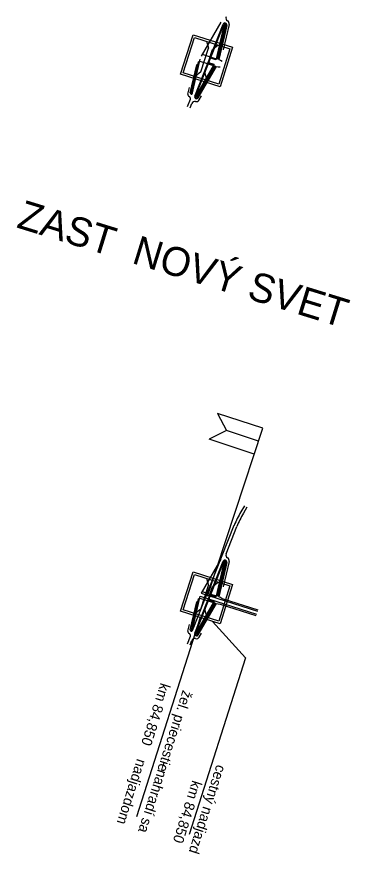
# Model space of a CAD drawing. Extents: x -566241 to -446826, y -1330151 to -1274078.
# Drawn here: x -545740 to -544934, y -1276105 to -1274078 of the extents above; entities that cross this region are included whole.
import ezdxf

# ---------------------------------------------------------------- set-up
doc = ezdxf.new("R2010")
doc.units = 0
for name, color, linetype in [('1-POPIS', 7, 'Continuous'), ('priecestia', 7, 'Continuous'), ('STANICE', 7, 'Continuous')]:
    doc.layers.add(name, color=color, linetype=linetype)

msp = doc.modelspace()

# ---------------------------------------------------------------- linework, layer by layer
at = {"layer": '1-POPIS'}
for p, q in [((-545294.7, -1274211.5), (-545276.5, -1274154.3)), ((-545281.4, -1274137), (-545276.5, -1274154.3)), ((-545266.9, -1274157.3), (-545252.8, -1274146.1)), ((-545285.2, -1274214.5), (-545266.9, -1274157.3)), ((-545304.6, -1274194.3), (-545301.4, -1274192.2)), ((-545300.1, -1274186.8), (-545297.3, -1274185.3)), ((-545294.7, -1274211.5), (-545308.8, -1274222.7)), ((-545285.2, -1274214.5), (-545280.2, -1274231.8)), ((-545281.4, -1275437), (-545276.5, -1275454.3)), ((-545266.9, -1275457.3), (-545252.8, -1275446.1)), ((-545294.7, -1275511.5), (-545276.5, -1275454.3)), ((-545285.2, -1275514.5), (-545266.9, -1275457.3)), ((-545304.6, -1275494.3), (-545301.4, -1275492.2)), ((-545300.1, -1275486.8), (-545297.3, -1275485.3)), ((-545294.7, -1275511.5), (-545308.8, -1275522.7)), ((-545285.2, -1275514.5), (-545280.2, -1275531.8)), ((-545296, -1275532), (-545449.9, -1276014.7)), ((-545186.5, -1275630), (-545266.6, -1275541.4)), ((-545186.5, -1275630), (-545322.8, -1276057.3))]:
    msp.add_line(p, q, dxfattribs=at)
for points in [[(-545238.4, -1274095.8), (-545236.7, -1274099.4), (-545233.7, -1274097.7)], [(-545264.1, -1274195.9), (-545264.2, -1274201), (-545259.2, -1274197.4)], [(-545252.9, -1274181), (-545254.6, -1274177.1), (-545257.7, -1274179.5)], [(-545315.9, -1274265.1), (-545317.6, -1274262.4), (-545320.2, -1274263.4)], [(-545307.9, -1274271.7), (-545304, -1274270), (-545303.3, -1274273.5)], [(-545238.4, -1275395.8), (-545236.7, -1275399.4), (-545233.7, -1275397.7)], [(-545252.9, -1275481), (-545254.6, -1275477.1), (-545257.7, -1275479.5)], [(-545264.1, -1275495.9), (-545264.2, -1275501), (-545259.2, -1275497.4)], [(-545315.9, -1275565.1), (-545317.6, -1275562.4), (-545320.2, -1275563.4)], [(-545307.9, -1275571.7), (-545304, -1275570), (-545303.3, -1275573.5)]]:
    msp.add_lwpolyline(points, dxfattribs=at)
for points in [[(-545313.3, -1274121.6), (-545218, -1274151.9), (-545248.4, -1274247.2), (-545343.6, -1274216.8)], [(-545310, -1274127.9), (-545224.3, -1274155.2), (-545251.6, -1274240.9), (-545337.4, -1274213.6)], [(-545313.3, -1275421.6), (-545218, -1275451.9), (-545248.4, -1275547.2), (-545343.6, -1275516.8)], [(-545310, -1275427.9), (-545224.3, -1275455.2), (-545251.6, -1275540.9), (-545337.4, -1275513.6)]]:
    msp.add_lwpolyline(points, close=True, dxfattribs=at)
for centre, radius, start, end in [((-545236.5, -1274097.7), 4.7, 347.0136, 158.4519), ((-545236.5, -1274097.7), 2.7, 347.0136, 158.4519), ((-545226.3, -1274080.9), 8, 158.4519, 240.8481), ((-545234.1, -1274094.8), 8, 347.0136, 60.8481), ((-545321.3, -1274266.2), 5, 166.9081, 250.1701), ((-545324.7, -1274275.6), 5, 338.4519, 70.1701), ((-545317.4, -1274262.5), 3, 166.9081, 338.4519), ((-545305.2, -1274271.6), 4.7, 158.4519, 329.9957), ((-545305.2, -1274271.6), 2.7, 158.4519, 329.9957), ((-545309.2, -1274290.9), 8, 76.0327, 158.4519), ((-545305.4, -1274275.4), 8, 256.0327, 329.9957), ((-545236.5, -1275397.7), 4.7, 347.0136, 158.4519), ((-545226.3, -1275380.9), 8, 158.4519, 240.8481), ((-545234.1, -1275394.8), 8, 347.0136, 60.8481), ((-545236.5, -1275397.7), 2.7, 347.0136, 158.4519), ((-545321.3, -1275566.2), 5, 166.9081, 250.1701), ((-545324.7, -1275575.6), 5, 338.4519, 70.1701), ((-545317.4, -1275562.5), 3, 166.9081, 338.4519), ((-545305.2, -1275571.6), 4.7, 158.4519, 329.9957), ((-545305.2, -1275571.6), 2.7, 158.4519, 329.9957), ((-545309.2, -1275590.9), 8, 76.0327, 158.4519), ((-545305.4, -1275575.4), 8, 256.0327, 329.9957)]:
    msp.add_arc(centre, radius, start, end, dxfattribs=at)
at = {"layer": 'priecestia'}
for p, q in [((-545246.5, -1274091.1), (-545294, -1274173.1)), ((-545238.4, -1274095.8), (-545257.7, -1274179.5)), ((-545309.5, -1274269.9), (-545240.9, -1274096)), ((-545307.7, -1274270.6), (-545239, -1274096.7)), ((-545236.7, -1274099.4), (-545254.6, -1274177.1)), ((-545233.9, -1274098.3), (-545252.9, -1274181)), ((-545231.9, -1274098.8), (-545251, -1274181.6)), ((-545226.3, -1274096.6), (-545240.4, -1274157.7)), ((-545291.5, -1274168.7), (-545257.7, -1274179.5)), ((-545270.4, -1274177), (-545270.9, -1274178.4)), ((-545270.4, -1274177), (-545270.7, -1274176.9)), ((-545258, -1274180.9), (-545270.4, -1274177)), ((-545320.3, -1274261.8), (-545304.6, -1274194.3)), ((-545317.6, -1274262.4), (-545300.1, -1274186.8)), ((-545315.9, -1274265.1), (-545296.2, -1274180.4)), ((-545307.9, -1274271.7), (-545264.1, -1274195.9)), ((-545297.3, -1274185.3), (-545259.2, -1274197.4)), ((-545275.7, -1274190.6), (-545276, -1274190.5)), ((-545275.2, -1274189.2), (-545275.7, -1274190.6)), ((-545263.3, -1274194.5), (-545275.7, -1274190.6)), ((-545275.2, -1274189.2), (-545275.5, -1274189.1)), ((-545275, -1274189.2), (-545275.5, -1274190.7)), ((-545262.9, -1274193.1), (-545275.2, -1274189.2)), ((-545274.8, -1274189.3), (-545275.2, -1274190.7)), ((-545274.5, -1274189.4), (-545275, -1274190.8)), ((-545274.3, -1274189.5), (-545274.7, -1274190.9)), ((-545274, -1274189.5), (-545274.5, -1274191)), ((-545273.8, -1274189.6), (-545274.3, -1274191)), ((-545273.6, -1274189.7), (-545274, -1274191.1)), ((-545273.3, -1274189.8), (-545273.8, -1274191.2)), ((-545273.1, -1274189.8), (-545273.5, -1274191.3)), ((-545272.9, -1274189.9), (-545273.3, -1274191.4)), ((-545271.9, -1274190.2), (-545272.4, -1274191.7)), ((-545271.7, -1274190.3), (-545272.1, -1274191.7)), ((-545271.4, -1274190.4), (-545271.9, -1274191.8)), ((-545271.2, -1274190.5), (-545271.6, -1274191.9)), ((-545271, -1274190.5), (-545271.4, -1274192)), ((-545270.9, -1274178.4), (-545271.2, -1274178.3)), ((-545270.7, -1274190.6), (-545271.2, -1274192)), ((-545258.5, -1274182.4), (-545270.9, -1274178.4)), ((-545270.5, -1274190.7), (-545270.9, -1274192.1)), ((-545270.2, -1274190.8), (-545270.7, -1274192.2)), ((-545270.2, -1274177.1), (-545270.6, -1274178.5)), ((-545270, -1274190.8), (-545270.5, -1274192.3)), ((-545270, -1274177.1), (-545270.4, -1274178.6)), ((-545269.7, -1274177.2), (-545270.2, -1274178.6)), ((-545269.8, -1274190.9), (-545270.2, -1274192.3)), ((-545269.5, -1274191), (-545270, -1274192.4)), ((-545269.5, -1274177.3), (-545269.9, -1274178.7)), ((-545269.2, -1274177.4), (-545269.7, -1274178.8)), ((-545269, -1274177.4), (-545269.5, -1274178.9)), ((-545268.8, -1274177.5), (-545269.2, -1274179)), ((-545268.5, -1274177.6), (-545269, -1274179)), ((-545268.6, -1274191.3), (-545269, -1274192.7)), ((-545268.3, -1274191.4), (-545268.8, -1274192.8)), ((-545268.3, -1274177.7), (-545268.7, -1274179.1)), ((-545268, -1274177.7), (-545268.5, -1274179.2)), ((-545268.1, -1274191.4), (-545268.5, -1274192.9)), ((-545267.9, -1274191.5), (-545268.3, -1274192.9)), ((-545267.6, -1274191.6), (-545268.1, -1274193)), ((-545267.4, -1274191.7), (-545267.8, -1274193.1)), ((-545267.1, -1274178.1), (-545267.6, -1274179.5)), ((-545267.1, -1274191.7), (-545267.6, -1274193.2)), ((-545266.9, -1274191.8), (-545267.4, -1274193.3)), ((-545266.9, -1274178.1), (-545267.3, -1274179.6)), ((-545266.6, -1274178.2), (-545267.1, -1274179.6)), ((-545266.7, -1274191.9), (-545267.1, -1274193.3)), ((-545266.4, -1274192), (-545266.9, -1274193.4)), ((-545266.4, -1274178.3), (-545266.8, -1274179.7)), ((-545266.1, -1274178.4), (-545266.6, -1274179.8)), ((-545266.2, -1274192.1), (-545266.6, -1274193.5)), ((-545265.9, -1274178.4), (-545266.4, -1274179.9)), ((-545265.7, -1274178.5), (-545266.1, -1274179.9)), ((-545265.4, -1274178.6), (-545265.9, -1274180)), ((-545265.2, -1274192.4), (-545265.7, -1274193.8)), ((-545265.2, -1274178.7), (-545265.6, -1274180.1)), ((-545265, -1274192.4), (-545265.5, -1274193.9)), ((-545265, -1274178.7), (-545265.4, -1274180.2)), ((-545264.7, -1274178.8), (-545265.2, -1274180.2)), ((-545264.8, -1274192.5), (-545265.2, -1274193.9)), ((-545264.5, -1274192.6), (-545265, -1274194)), ((-545264.3, -1274192.7), (-545264.7, -1274194.1)), ((-545264, -1274192.7), (-545264.5, -1274194.2)), ((-545263.8, -1274192.8), (-545264.3, -1274194.2)), ((-545263.8, -1274179.1), (-545264.2, -1274180.5)), ((-545263.5, -1274179.2), (-545264, -1274180.6)), ((-545263.6, -1274192.9), (-545264, -1274194.3)), ((-545263.3, -1274193), (-545263.8, -1274194.4)), ((-545263.3, -1274179.3), (-545263.7, -1274180.7)), ((-545263, -1274179.3), (-545263.5, -1274180.8)), ((-545263.1, -1274193), (-545263.5, -1274194.5)), ((-545262.8, -1274179.4), (-545263.3, -1274180.8)), ((-545262.9, -1274193.1), (-545263.3, -1274194.5)), ((-545262.6, -1274179.5), (-545263, -1274180.9)), ((-545262.3, -1274179.6), (-545262.8, -1274181)), ((-545262.1, -1274179.6), (-545262.5, -1274181.1)), ((-545261.9, -1274179.7), (-545262.3, -1274181.2)), ((-545261.6, -1274179.8), (-545262.1, -1274181.2)), ((-545261.4, -1274179.9), (-545261.8, -1274181.3)), ((-545260.4, -1274180.2), (-545260.9, -1274181.6)), ((-545260.2, -1274180.3), (-545260.6, -1274181.7)), ((-545259.9, -1274180.3), (-545260.4, -1274181.8)), ((-545259.7, -1274180.4), (-545260.2, -1274181.8)), ((-545259.5, -1274180.5), (-545259.9, -1274181.9)), ((-545259.2, -1274180.6), (-545259.7, -1274182)), ((-545259, -1274180.6), (-545259.5, -1274182.1)), ((-545258.8, -1274180.7), (-545259.2, -1274182.1)), ((-545258.5, -1274180.8), (-545259, -1274182.2)), ((-545258.3, -1274180.9), (-545258.7, -1274182.3)), ((-545258, -1274180.9), (-545258.5, -1274182.4)), ((-545251, -1274181.6), (-545247.1, -1274182.9)), ((-545247.1, -1274182.9), (-545242.8, -1274185.8)), ((-545304, -1274270), (-545264.2, -1274201)), ((-545302.8, -1274273), (-545259.2, -1274197.4)), ((-545301.1, -1274274), (-545257.2, -1274198)), ((-545257.2, -1274198), (-545253.2, -1274199.3)), ((-545253.2, -1274199.3), (-545248, -1274199.4)), ((-545326.2, -1274265.1), (-545322.4, -1274248.9)), ((-545327.2, -1274295.4), (-545320, -1274277.4)), ((-545307.7, -1274275.4), (-545307.7, -1274275.4)), ((-545298.4, -1274279.4), (-545292.8, -1274269.6)), ((-545320.6, -1274298), (-545316.7, -1274288)), ((-545189.4, -1275261.7), (-545197.9, -1275276.1)), ((-545183.4, -1275265.3), (-545191.6, -1275279.2)), ((-545314.6, -1275563.6), (-545214, -1275308.9)), ((-545233.7, -1275377.9), (-545207.7, -1275312)), ((-545246.5, -1275391.1), (-545294, -1275473.1)), ((-545309.5, -1275569.9), (-545240.9, -1275396)), ((-545307.7, -1275570.6), (-545239, -1275396.7)), ((-545238.4, -1275395.8), (-545257.7, -1275479.5)), ((-545236.7, -1275399.4), (-545254.6, -1275477.1)), ((-545233.9, -1275398.3), (-545252.9, -1275481)), ((-545231.9, -1275398.8), (-545251, -1275481.6)), ((-545226.3, -1275396.6), (-545240.4, -1275457.7)), ((-545294, -1275473.1), (-545158, -1275516.5)), ((-545291.5, -1275468.7), (-545257.7, -1275479.5)), ((-545320.3, -1275561.8), (-545304.6, -1275494.3)), ((-545317.6, -1275562.4), (-545300.1, -1275486.8)), ((-545315.9, -1275565.1), (-545296.2, -1275480.4)), ((-545297.3, -1275485.3), (-545259.2, -1275497.4)), ((-545296.2, -1275480.4), (-545160.3, -1275523.7)), ((-545275.7, -1275490.6), (-545276, -1275490.5)), ((-545275.2, -1275489.2), (-545275.7, -1275490.6)), ((-545263.3, -1275494.5), (-545275.7, -1275490.6)), ((-545275.2, -1275489.2), (-545275.5, -1275489.1)), ((-545275, -1275489.2), (-545275.5, -1275490.7)), ((-545262.9, -1275493.1), (-545275.2, -1275489.2)), ((-545274.8, -1275489.3), (-545275.2, -1275490.7)), ((-545274.5, -1275489.4), (-545275, -1275490.8)), ((-545274.3, -1275489.5), (-545274.7, -1275490.9)), ((-545274, -1275489.5), (-545274.5, -1275491)), ((-545273.8, -1275489.6), (-545274.3, -1275491)), ((-545273.6, -1275489.7), (-545274, -1275491.1)), ((-545273.3, -1275489.8), (-545273.8, -1275491.2)), ((-545273.1, -1275489.8), (-545273.5, -1275491.3)), ((-545272.9, -1275489.9), (-545273.3, -1275491.4)), ((-545271.9, -1275490.2), (-545272.4, -1275491.7)), ((-545271.7, -1275490.3), (-545272.1, -1275491.7)), ((-545271.4, -1275490.4), (-545271.9, -1275491.8)), ((-545271.2, -1275490.5), (-545271.6, -1275491.9)), ((-545271, -1275490.5), (-545271.4, -1275492)), ((-545270.9, -1275478.4), (-545271.2, -1275478.3)), ((-545270.7, -1275490.6), (-545271.2, -1275492)), ((-545270.4, -1275477), (-545270.9, -1275478.4)), ((-545258.5, -1275482.4), (-545270.9, -1275478.4)), ((-545270.5, -1275490.7), (-545270.9, -1275492.1)), ((-545270.4, -1275477), (-545270.7, -1275476.9)), ((-545270.2, -1275490.8), (-545270.7, -1275492.2)), ((-545270.2, -1275477.1), (-545270.6, -1275478.5)), ((-545270, -1275490.8), (-545270.5, -1275492.3)), ((-545258, -1275480.9), (-545270.4, -1275477)), ((-545270, -1275477.1), (-545270.4, -1275478.6)), ((-545269.7, -1275477.2), (-545270.2, -1275478.6)), ((-545269.8, -1275490.9), (-545270.2, -1275492.3)), ((-545269.5, -1275491), (-545270, -1275492.4)), ((-545269.5, -1275477.3), (-545269.9, -1275478.7)), ((-545269.2, -1275477.4), (-545269.7, -1275478.8)), ((-545269, -1275477.4), (-545269.5, -1275478.9)), ((-545268.8, -1275477.5), (-545269.2, -1275479)), ((-545268.5, -1275477.6), (-545269, -1275479)), ((-545268.6, -1275491.3), (-545269, -1275492.7)), ((-545268.3, -1275491.4), (-545268.8, -1275492.8)), ((-545268.3, -1275477.7), (-545268.7, -1275479.1)), ((-545268, -1275477.7), (-545268.5, -1275479.2)), ((-545268.1, -1275491.4), (-545268.5, -1275492.9)), ((-545267.9, -1275491.5), (-545268.3, -1275492.9)), ((-545267.6, -1275491.6), (-545268.1, -1275493)), ((-545267.4, -1275491.7), (-545267.8, -1275493.1)), ((-545267.1, -1275478.1), (-545267.6, -1275479.5)), ((-545267.1, -1275491.7), (-545267.6, -1275493.2)), ((-545266.9, -1275491.8), (-545267.4, -1275493.3)), ((-545266.9, -1275478.1), (-545267.3, -1275479.6)), ((-545266.6, -1275478.2), (-545267.1, -1275479.6)), ((-545266.7, -1275491.9), (-545267.1, -1275493.3)), ((-545266.4, -1275492), (-545266.9, -1275493.4)), ((-545266.4, -1275478.3), (-545266.8, -1275479.7)), ((-545266.1, -1275478.4), (-545266.6, -1275479.8)), ((-545266.2, -1275492.1), (-545266.6, -1275493.5)), ((-545265.9, -1275478.4), (-545266.4, -1275479.9)), ((-545265.7, -1275478.5), (-545266.1, -1275479.9)), ((-545265.4, -1275478.6), (-545265.9, -1275480)), ((-545265.2, -1275492.4), (-545265.7, -1275493.8)), ((-545265.2, -1275478.7), (-545265.6, -1275480.1)), ((-545265, -1275492.4), (-545265.5, -1275493.9)), ((-545265, -1275478.7), (-545265.4, -1275480.2)), ((-545264.7, -1275478.8), (-545265.2, -1275480.2)), ((-545264.8, -1275492.5), (-545265.2, -1275493.9)), ((-545264.5, -1275492.6), (-545265, -1275494)), ((-545264.3, -1275492.7), (-545264.7, -1275494.1)), ((-545264, -1275492.7), (-545264.5, -1275494.2)), ((-545263.8, -1275492.8), (-545264.3, -1275494.2)), ((-545263.8, -1275479.1), (-545264.2, -1275480.5)), ((-545263.5, -1275479.2), (-545264, -1275480.6)), ((-545263.6, -1275492.9), (-545264, -1275494.3)), ((-545263.3, -1275493), (-545263.8, -1275494.4)), ((-545263.3, -1275479.3), (-545263.7, -1275480.7)), ((-545263, -1275479.3), (-545263.5, -1275480.8)), ((-545263.1, -1275493), (-545263.5, -1275494.5)), ((-545262.8, -1275479.4), (-545263.3, -1275480.8)), ((-545262.9, -1275493.1), (-545263.3, -1275494.5)), ((-545262.6, -1275479.5), (-545263, -1275480.9)), ((-545262.3, -1275479.6), (-545262.8, -1275481)), ((-545262.1, -1275479.6), (-545262.5, -1275481.1)), ((-545261.9, -1275479.7), (-545262.3, -1275481.2)), ((-545261.6, -1275479.8), (-545262.1, -1275481.2)), ((-545261.4, -1275479.9), (-545261.8, -1275481.3)), ((-545260.4, -1275480.2), (-545260.9, -1275481.6)), ((-545260.2, -1275480.3), (-545260.6, -1275481.7)), ((-545259.9, -1275480.3), (-545260.4, -1275481.8)), ((-545259.7, -1275480.4), (-545260.2, -1275481.8)), ((-545259.5, -1275480.5), (-545259.9, -1275481.9)), ((-545259.2, -1275480.6), (-545259.7, -1275482)), ((-545259, -1275480.6), (-545259.5, -1275482.1)), ((-545258.8, -1275480.7), (-545259.2, -1275482.1)), ((-545258.5, -1275480.8), (-545259, -1275482.2)), ((-545258.3, -1275480.9), (-545258.7, -1275482.3)), ((-545258, -1275480.9), (-545258.5, -1275482.4)), ((-545251, -1275481.6), (-545247.1, -1275482.9)), ((-545247.1, -1275482.9), (-545242.8, -1275485.8)), ((-545242.8, -1275485.8), (-545156.9, -1275513.2)), ((-545307.9, -1275571.7), (-545264.1, -1275495.9)), ((-545304, -1275570), (-545264.2, -1275501)), ((-545302.8, -1275573), (-545259.2, -1275497.4)), ((-545301.1, -1275574), (-545257.2, -1275498)), ((-545257.2, -1275498), (-545253.2, -1275499.3)), ((-545253.2, -1275499.3), (-545248, -1275499.4)), ((-545248, -1275499.4), (-545161.4, -1275527)), ((-545326.2, -1275565.1), (-545322.4, -1275548.9)), ((-545307.7, -1275575.4), (-545307.7, -1275575.4)), ((-545298.4, -1275579.4), (-545292.8, -1275569.6)), ((-545327.2, -1275595.4), (-545320, -1275577.4)), ((-545320.6, -1275598), (-545316.7, -1275588))]:
    msp.add_line(p, q, dxfattribs=at)
for centre in [(-545000.1, -1275393.4), (-544993.8, -1275396.5)]:
    msp.add_arc(centre, 230, 149.3459, 158.4519, dxfattribs=at)
at = {"layer": 'STANICE'}
for p, q in [((-545145.1, -1275073.6), (-545254.1, -1275037.9)), ((-545254.1, -1275037.9), (-545233, -1275079.6)), ((-545278.3, -1275480.3), (-545145.1, -1275073.6)), ((-545233, -1275079.6), (-545274.7, -1275100.7)), ((-545155.4, -1275105), (-545233, -1275079.6)), ((-545165.7, -1275136.4), (-545274.7, -1275100.7))]:
    msp.add_line(p, q, dxfattribs=at)

# ---------------------------------------------------------------- texts
at = {"layer": '1-POPIS'}
for s, rotation, p in [('km 84,850', 252.3161, (-545391.9, -1275688.8)), ('žel. priecestie', 252.3161, (-545338.2, -1275706.4)), ('nadjazdom', 252.3169, (-545448.7, -1275872.4)), ('- nahradí sa', 252.3161, (-545392.3, -1275878.6)), ('cestný nadjazd', 252.3161, (-545256.7, -1275886.7)), ('km 84,850', 252.3161, (-545315.2, -1275924.7))]:
    msp.add_text(s, height=25, rotation=rotation, dxfattribs=at).set_placement(p)
at = {"layer": 'STANICE'}
msp.add_text('ZAST  NOVÝ SVET', height=70, rotation=342.8511, dxfattribs=at).set_placement((-545742.5, -1274587.4))

doc.saveas('drawing.dxf')
